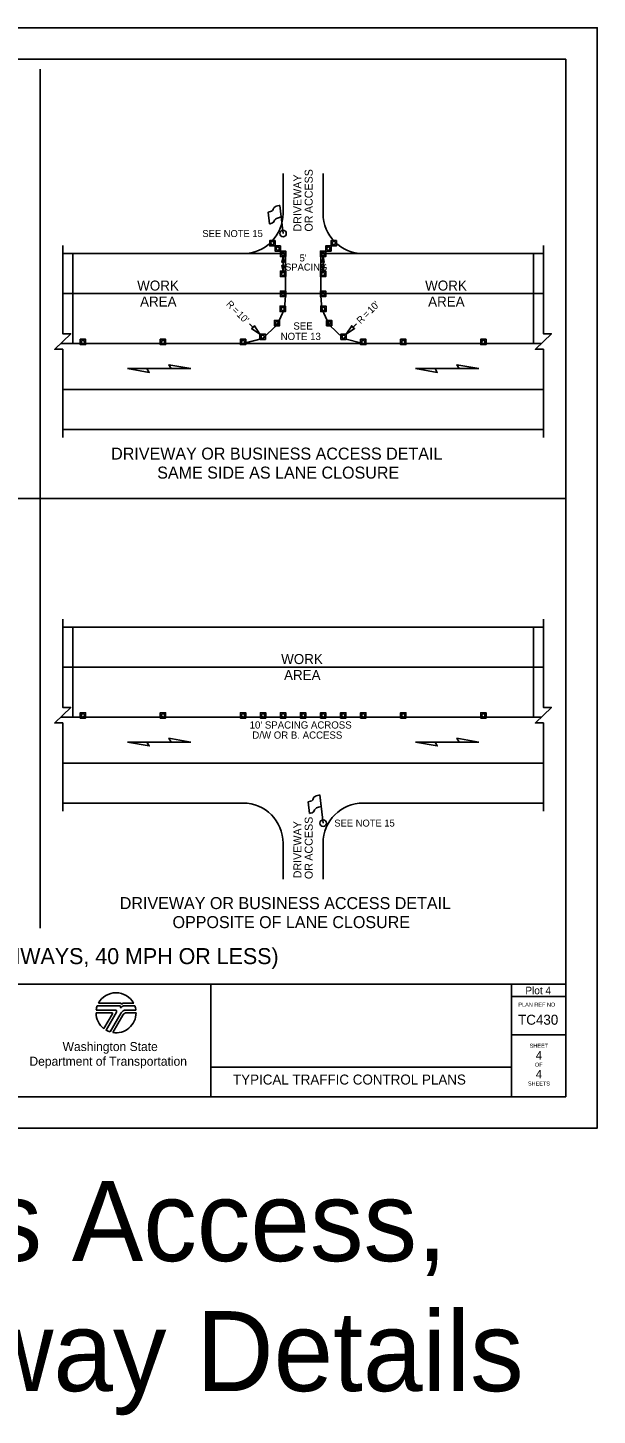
# Model space of a CAD drawing. Extents: x 99999.1 to 100095.7, y 99995 to 100010.7.
# Drawn here: x 100070.38 to 100076.06, y 99996.82 to 100010.69 of the extents above; entities that cross this region are included whole.
import ezdxf

# ---------------------------------------------------------------- set-up
doc = ezdxf.new("R2010")
doc.units = 0
for name, color, linetype in [('RD_ED_DrivewayEdge', 7, 'Continuous'), ('RD_ED_ShoulderPavedEdge', 7, 'Continuous'), ('RD_MK_LineEdgeWhite', 7, 'Continuous'), ('RD_MK_LineSkipCenter', 7, 'Continuous'), ('SH_DE_DetailHeading1Text', 7, 'Continuous'), ('SH_DE_DetailHeading2Text', 7, 'Continuous'), ('SH_GI_PlotLimits', 7, 'Continuous'), ('SH_GI_SheetBorder', 7, 'Continuous'), ('SH_GI_SheetLocationText', 7, 'Continuous'), ('SH_GI_SheetTextInCells', 7, 'Continuous'), ('SH_GI_TitleBlockText', 7, 'Continuous'), ('SH_GI_WSDOTLogo', 7, 'Continuous'), ('TR_WZ_FlaggingStation', 7, 'Continuous'), ('TR_WZ_TrafficCone', 7, 'Continuous'), ('TR_WZ_WorkAreaLabel', 7, 'Continuous'), ('TR_WZ_WorkZoneDetails', 7, 'Continuous'), ('TR_WZ_WorkZoneTextCurrent', 7, 'Continuous')]:
    doc.layers.add(name, color=color, linetype=linetype)

msp = doc.modelspace()

# ---------------------------------------------------------------- linework, layer by layer
at = {"layer": 'RD_ED_DrivewayEdge'}
for p, q in [((100072.925, 100008.83), (100072.925, 100009.23)), ((100073.325, 100008.83), (100073.325, 100009.23)), ((100072.925, 100002.536), (100072.925, 100002.176)), ((100073.325, 100002.536), (100073.325, 100002.176))]:
    msp.add_line(p, q, dxfattribs=at)
for centre, start, end in [((100072.525, 100008.83), 270, 0), ((100073.725, 100008.83), 180, 270), ((100072.525, 100002.536), 0, 90), ((100073.725, 100002.536), 90, 180)]:
    msp.add_arc(centre, 0.4, start, end, dxfattribs=at)
at = {"layer": 'RD_ED_ShoulderPavedEdge'}
for p, q in [((100070.725, 100008.43), (100072.525, 100008.43)), ((100073.725, 100008.43), (100075.525, 100008.43)), ((100070.725, 100006.67), (100075.525, 100006.67)), ((100070.725, 100004.696), (100075.525, 100004.696)), ((100070.725, 100002.936), (100072.525, 100002.936)), ((100073.725, 100002.936), (100075.525, 100002.936))]:
    msp.add_line(p, q, dxfattribs=at)
at = {"layer": 'RD_MK_LineEdgeWhite'}
for p, q in [((100070.725, 100008.03), (100075.525, 100008.03)), ((100070.725, 100007.07), (100075.525, 100007.07)), ((100070.725, 100004.296), (100075.525, 100004.296)), ((100070.725, 100003.336), (100075.525, 100003.336))]:
    msp.add_line(p, q, dxfattribs=at)
at = {"layer": 'RD_MK_LineSkipCenter'}
for points in [[(100075.504, 100007.53), (100070.704, 100007.53)], [(100075.504, 100003.796), (100070.704, 100003.796)]]:
    msp.add_lwpolyline(points, dxfattribs=at)
at = {"layer": 'SH_GI_PlotLimits'}
msp.add_lwpolyline([(100059.062, 99999.687), (100076.062, 99999.687), (100076.062, 100010.687), (100059.062, 100010.687)], close=True, dxfattribs=at)
at = {"layer": 'SH_GI_SheetBorder'}
for p, q in [((100060, 100010.375), (100075.75, 100010.375)), ((100075.75, 100010.375), (100075.75, 100000)), ((100060, 100001.126), (100075.75, 100001.126)), ((100072.205, 100001.126), (100072.205, 100000)), ((100075.208, 100001.126), (100075.208, 100000)), ((100075.208, 100001.001), (100075.75, 100001.001)), ((100075.208, 100000.618), (100075.75, 100000.618)), ((100072.205, 100000.295), (100075.208, 100000.295)), ((100060, 100000), (100075.75, 100000))]:
    msp.add_line(p, q, dxfattribs=at)
at = {"layer": 'SH_GI_WSDOTLogo'}
for p, q in [((100071.059, 100000.866), (100071.25, 100000.866)), ((100071.289, 100000.909), (100071.07, 100000.909)), ((100071.303, 100000.935), (100071.081, 100000.935)), ((100071.433, 100000.935), (100071.335, 100000.935)), ((100071.445, 100000.909), (100071.343, 100000.909)), ((100071.343, 100000.909), (100071.343, 100000.909)), ((100071.356, 100000.866), (100071.456, 100000.866)), ((100071.057, 100000.84), (100071.215, 100000.84)), ((100071.222, 100000.828), (100071.136, 100000.681)), ((100071.261, 100000.846), (100071.157, 100000.667)), ((100071.199, 100000.649), (100071.309, 100000.839)), ((100071.224, 100000.643), (100071.324, 100000.816)), ((100071.365, 100000.839), (100071.457, 100000.839))]:
    msp.add_line(p, q, dxfattribs=at)
for centre, radius, start, end in [((100071.257, 100000.84), 0.2, 28.4787, 151.532), ((100071.257, 100000.84), 0.2, 159.696, 172.5057), ((100071.25, 100000.853), 0.0131, 329.7683, 90), ((100071.289, 100000.895), 0.0148, 327.8418, 89.9985), ((100071.343, 100000.861), 0.0484, 89.9953, 147.8238), ((100071.303, 100000.926), 0.00903, 329.8742, 90.0033), ((100071.356, 100000.812), 0.0542, 90, 149.9974), ((100071.335, 100000.907), 0.0287, 90.0072, 148.1676), ((100071.257, 100000.84), 0.2, 7.4943, 20.2941), ((100071.257, 100000.84), 0.2, 179.9986, 232.8433), ((100071.215, 100000.832), 0.0082, 329.7436, 90), ((100071.257, 100000.84), 0.2, 260.5455, 359.8086), ((100071.365, 100000.792), 0.0476, 90, 150.0543), ((100071.257, 100000.84), 0.2, 239.7929, 253.0448)]:
    msp.add_arc(centre, radius, start, end, dxfattribs=at)
at = {"layer": 'TR_WZ_FlaggingStation'}
for p, q in [((100072.906, 100008.797), (100072.893, 100008.912)), ((100072.925, 100008.63), (100072.893, 100008.911)), ((100072.775, 100008.844), (100072.788, 100008.727)), ((100072.906, 100008.797), (100072.906, 100008.797)), ((100073.175, 100002.949), (100073.188, 100002.832)), ((100073.325, 100002.736), (100073.293, 100003.017)), ((100073.306, 100002.903), (100073.293, 100003.017)), ((100073.306, 100002.903), (100073.306, 100002.903))]:
    msp.add_line(p, q, dxfattribs=at)
for points in [[(100072.893, 100008.912), (100072.887, 100008.91), (100072.869, 100008.907), (100072.856, 100008.903), (100072.846, 100008.897), (100072.837, 100008.892), (100072.832, 100008.885), (100072.827, 100008.877), (100072.827, 100008.871), (100072.821, 100008.862), (100072.811, 100008.854), (100072.798, 100008.849), (100072.775, 100008.844)], [(100072.788, 100008.727), (100072.796, 100008.728), (100072.814, 100008.733), (100072.83, 100008.743), (100072.836, 100008.754), (100072.84, 100008.764), (100072.849, 100008.775), (100072.86, 100008.781), (100072.878, 100008.788), (100072.906, 100008.797)], [(100073.293, 100003.017), (100073.287, 100003.016), (100073.269, 100003.012), (100073.256, 100003.008), (100073.246, 100003.002), (100073.237, 100002.997), (100073.232, 100002.991), (100073.227, 100002.983), (100073.227, 100002.977), (100073.221, 100002.967), (100073.211, 100002.96), (100073.198, 100002.955), (100073.175, 100002.949)], [(100073.188, 100002.832), (100073.196, 100002.834), (100073.214, 100002.838), (100073.23, 100002.849), (100073.236, 100002.859), (100073.24, 100002.87), (100073.249, 100002.88), (100073.26, 100002.887), (100073.278, 100002.894), (100073.306, 100002.903)]]:
    msp.add_lwpolyline(points, dxfattribs=at)
for centre in [(100072.925, 100008.63), (100073.325, 100002.736)]:
    msp.add_circle(centre, 0.0325, dxfattribs=at)
at = {"layer": 'TR_WZ_TrafficCone'}
for points in [[(100072.845, 100008.56), (100072.845, 100008.507), (100072.792, 100008.507), (100072.792, 100008.56), (100072.845, 100008.56)], [(100072.792, 100008.56), (100072.792, 100008.507), (100072.845, 100008.507), (100072.845, 100008.56), (100072.792, 100008.56)], [(100072.898, 100008.507), (100072.898, 100008.454), (100072.845, 100008.454), (100072.845, 100008.507), (100072.898, 100008.507)], [(100072.845, 100008.507), (100072.845, 100008.454), (100072.898, 100008.454), (100072.898, 100008.507), (100072.845, 100008.507)], [(100073.352, 100008.507), (100073.352, 100008.454), (100073.405, 100008.454), (100073.405, 100008.507), (100073.352, 100008.507)], [(100073.405, 100008.507), (100073.405, 100008.454), (100073.352, 100008.454), (100073.352, 100008.507), (100073.405, 100008.507)], [(100073.405, 100008.56), (100073.405, 100008.507), (100073.458, 100008.507), (100073.458, 100008.56), (100073.405, 100008.56)], [(100073.458, 100008.56), (100073.458, 100008.507), (100073.405, 100008.507), (100073.405, 100008.56), (100073.458, 100008.56)], [(100072.898, 100008.454), (100072.952, 100008.454), (100072.952, 100008.4), (100072.898, 100008.4), (100072.898, 100008.454)], [(100072.898, 100008.4), (100072.952, 100008.4), (100072.952, 100008.454), (100072.898, 100008.454), (100072.898, 100008.4)], [(100073.352, 100008.454), (100073.298, 100008.454), (100073.298, 100008.4), (100073.352, 100008.4), (100073.352, 100008.454)], [(100073.352, 100008.4), (100073.298, 100008.4), (100073.298, 100008.454), (100073.352, 100008.454), (100073.352, 100008.4)], [(100072.898, 100008.254), (100072.952, 100008.254), (100072.952, 100008.2), (100072.898, 100008.2), (100072.898, 100008.254)], [(100072.898, 100008.2), (100072.952, 100008.2), (100072.952, 100008.254), (100072.898, 100008.254), (100072.898, 100008.2)], [(100073.352, 100008.254), (100073.298, 100008.254), (100073.298, 100008.2), (100073.352, 100008.2), (100073.352, 100008.254)], [(100073.352, 100008.2), (100073.298, 100008.2), (100073.298, 100008.254), (100073.352, 100008.254), (100073.352, 100008.2)], [(100072.898, 100008.054), (100072.952, 100008.054), (100072.952, 100008), (100072.898, 100008), (100072.898, 100008.054)], [(100072.898, 100008), (100072.952, 100008), (100072.952, 100008.054), (100072.898, 100008.054), (100072.898, 100008)], [(100073.352, 100008.054), (100073.298, 100008.054), (100073.298, 100008), (100073.352, 100008), (100073.352, 100008.054)], [(100073.352, 100008), (100073.298, 100008), (100073.298, 100008.054), (100073.352, 100008.054), (100073.352, 100008)], [(100072.896, 100007.904), (100072.949, 100007.904), (100072.949, 100007.85), (100072.896, 100007.85), (100072.896, 100007.904)], [(100072.896, 100007.85), (100072.949, 100007.85), (100072.949, 100007.904), (100072.896, 100007.904), (100072.896, 100007.85)], [(100073.354, 100007.904), (100073.301, 100007.904), (100073.301, 100007.85), (100073.354, 100007.85), (100073.354, 100007.904)], [(100073.354, 100007.85), (100073.301, 100007.85), (100073.301, 100007.904), (100073.354, 100007.904), (100073.354, 100007.85)], [(100072.838, 100007.762), (100072.891, 100007.762), (100072.891, 100007.708), (100072.838, 100007.708), (100072.838, 100007.762)], [(100072.838, 100007.708), (100072.891, 100007.708), (100072.891, 100007.762), (100072.838, 100007.762), (100072.838, 100007.708)], [(100073.412, 100007.762), (100073.359, 100007.762), (100073.359, 100007.708), (100073.412, 100007.708), (100073.412, 100007.762)], [(100073.412, 100007.708), (100073.359, 100007.708), (100073.359, 100007.762), (100073.412, 100007.762), (100073.412, 100007.708)], [(100070.899, 100007.574), (100070.952, 100007.574), (100070.952, 100007.52), (100070.899, 100007.52), (100070.899, 100007.574)], [(100070.899, 100007.52), (100070.952, 100007.52), (100070.952, 100007.574), (100070.899, 100007.574), (100070.899, 100007.52)], [(100071.699, 100007.574), (100071.752, 100007.574), (100071.752, 100007.52), (100071.699, 100007.52), (100071.699, 100007.574)], [(100071.699, 100007.52), (100071.752, 100007.52), (100071.752, 100007.574), (100071.699, 100007.574), (100071.699, 100007.52)], [(100072.499, 100007.574), (100072.552, 100007.574), (100072.552, 100007.52), (100072.499, 100007.52), (100072.499, 100007.574)], [(100072.499, 100007.52), (100072.552, 100007.52), (100072.552, 100007.574), (100072.499, 100007.574), (100072.499, 100007.52)], [(100072.694, 100007.625), (100072.748, 100007.625), (100072.748, 100007.571), (100072.694, 100007.571), (100072.694, 100007.625)], [(100072.694, 100007.571), (100072.748, 100007.571), (100072.748, 100007.625), (100072.694, 100007.625), (100072.694, 100007.571)], [(100073.556, 100007.625), (100073.502, 100007.625), (100073.502, 100007.571), (100073.556, 100007.571), (100073.556, 100007.625)], [(100073.556, 100007.571), (100073.502, 100007.571), (100073.502, 100007.625), (100073.556, 100007.625), (100073.556, 100007.571)], [(100073.699, 100007.574), (100073.752, 100007.574), (100073.752, 100007.52), (100073.699, 100007.52), (100073.699, 100007.574)], [(100073.699, 100007.52), (100073.752, 100007.52), (100073.752, 100007.574), (100073.699, 100007.574), (100073.699, 100007.52)], [(100074.099, 100007.574), (100074.152, 100007.574), (100074.152, 100007.52), (100074.099, 100007.52), (100074.099, 100007.574)], [(100074.099, 100007.52), (100074.152, 100007.52), (100074.152, 100007.574), (100074.099, 100007.574), (100074.099, 100007.52)], [(100074.899, 100007.574), (100074.952, 100007.574), (100074.952, 100007.52), (100074.899, 100007.52), (100074.899, 100007.574)], [(100074.899, 100007.52), (100074.952, 100007.52), (100074.952, 100007.574), (100074.899, 100007.574), (100074.899, 100007.52)], [(100070.899, 100003.839), (100070.952, 100003.839), (100070.952, 100003.786), (100070.899, 100003.786), (100070.899, 100003.839)], [(100070.899, 100003.786), (100070.952, 100003.786), (100070.952, 100003.839), (100070.899, 100003.839), (100070.899, 100003.786)], [(100071.699, 100003.839), (100071.752, 100003.839), (100071.752, 100003.786), (100071.699, 100003.786), (100071.699, 100003.839)], [(100071.699, 100003.786), (100071.752, 100003.786), (100071.752, 100003.839), (100071.699, 100003.839), (100071.699, 100003.786)], [(100072.499, 100003.839), (100072.552, 100003.839), (100072.552, 100003.786), (100072.499, 100003.786), (100072.499, 100003.839)], [(100072.499, 100003.786), (100072.552, 100003.786), (100072.552, 100003.839), (100072.499, 100003.839), (100072.499, 100003.786)], [(100072.699, 100003.839), (100072.752, 100003.839), (100072.752, 100003.786), (100072.699, 100003.786), (100072.699, 100003.839)], [(100072.699, 100003.786), (100072.752, 100003.786), (100072.752, 100003.839), (100072.699, 100003.839), (100072.699, 100003.786)], [(100072.899, 100003.839), (100072.952, 100003.839), (100072.952, 100003.786), (100072.899, 100003.786), (100072.899, 100003.839)], [(100072.899, 100003.786), (100072.952, 100003.786), (100072.952, 100003.839), (100072.899, 100003.839), (100072.899, 100003.786)], [(100073.099, 100003.839), (100073.152, 100003.839), (100073.152, 100003.786), (100073.099, 100003.786), (100073.099, 100003.839)], [(100073.099, 100003.786), (100073.152, 100003.786), (100073.152, 100003.839), (100073.099, 100003.839), (100073.099, 100003.786)], [(100073.299, 100003.839), (100073.352, 100003.839), (100073.352, 100003.786), (100073.299, 100003.786), (100073.299, 100003.839)], [(100073.299, 100003.786), (100073.352, 100003.786), (100073.352, 100003.839), (100073.299, 100003.839), (100073.299, 100003.786)], [(100073.499, 100003.839), (100073.552, 100003.839), (100073.552, 100003.786), (100073.499, 100003.786), (100073.499, 100003.839)], [(100073.499, 100003.786), (100073.552, 100003.786), (100073.552, 100003.839), (100073.499, 100003.839), (100073.499, 100003.786)], [(100073.699, 100003.839), (100073.752, 100003.839), (100073.752, 100003.786), (100073.699, 100003.786), (100073.699, 100003.839)], [(100073.699, 100003.786), (100073.752, 100003.786), (100073.752, 100003.839), (100073.699, 100003.839), (100073.699, 100003.786)], [(100074.099, 100003.839), (100074.152, 100003.839), (100074.152, 100003.786), (100074.099, 100003.786), (100074.099, 100003.839)], [(100074.099, 100003.786), (100074.152, 100003.786), (100074.152, 100003.839), (100074.099, 100003.839), (100074.099, 100003.786)], [(100074.899, 100003.839), (100074.952, 100003.839), (100074.952, 100003.786), (100074.899, 100003.786), (100074.899, 100003.839)], [(100074.899, 100003.786), (100074.952, 100003.786), (100074.952, 100003.839), (100074.899, 100003.839), (100074.899, 100003.786)]]:
    msp.add_lwpolyline(points, dxfattribs=at)
for centre in [(100072.818, 100008.534), (100072.872, 100008.48), (100073.378, 100008.48), (100073.432, 100008.534), (100072.925, 100008.427), (100073.325, 100008.427), (100072.925, 100008.227), (100073.325, 100008.227), (100072.925, 100008.027), (100073.325, 100008.027), (100072.922, 100007.877), (100073.328, 100007.877), (100072.865, 100007.735), (100073.385, 100007.735), (100070.926, 100007.547), (100071.726, 100007.547), (100072.526, 100007.547), (100072.721, 100007.598), (100073.529, 100007.598), (100073.726, 100007.547), (100074.126, 100007.547), (100074.926, 100007.547), (100070.926, 100003.813), (100071.726, 100003.813), (100072.526, 100003.813), (100072.726, 100003.813), (100072.926, 100003.813), (100073.126, 100003.813), (100073.326, 100003.813), (100073.526, 100003.813), (100073.726, 100003.813), (100074.126, 100003.813), (100074.926, 100003.813)]:
    msp.add_circle(centre, 0.0167, dxfattribs=at)
at = {"layer": 'TR_WZ_WorkZoneDetails'}
for p, q in [((100070.5, 100010.275), (100070.5, 100001.686)), ((100072.925, 100008.346), (100072.925, 100008.308)), ((100073.325, 100008.346), (100073.325, 100008.308)), ((100072.628, 100007.691), (100072.59, 100007.729)), ((100073.622, 100007.691), (100073.66, 100007.729)), ((100071.566, 100007.28), (100071.808, 100007.28)), ((100071.808, 100007.28), (100071.566, 100007.28)), ((100074.443, 100007.28), (100074.684, 100007.28)), ((100074.684, 100007.28), (100074.443, 100007.28)), ((100070.5, 100005.98), (100065.25, 100005.98)), ((100075.75, 100005.98), (100070.5, 100005.98)), ((100071.566, 100003.546), (100071.808, 100003.546)), ((100071.808, 100003.546), (100071.566, 100003.546)), ((100074.443, 100003.546), (100074.684, 100003.546)), ((100074.684, 100003.546), (100074.443, 100003.546))]:
    msp.add_line(p, q, dxfattribs=at)
for points in [[(100070.725, 100006.59), (100070.725, 100007.473), (100070.645, 100007.473), (100070.805, 100007.628), (100070.725, 100007.628), (100070.725, 100008.51)], [(100075.525, 100006.59), (100075.525, 100007.473), (100075.445, 100007.473), (100075.605, 100007.628), (100075.525, 100007.628), (100075.525, 100008.51)], [(100070.725, 100002.856), (100070.725, 100003.738), (100070.645, 100003.738), (100070.805, 100003.893), (100070.725, 100003.893), (100070.725, 100004.776)], [(100075.525, 100002.856), (100075.525, 100003.738), (100075.445, 100003.738), (100075.605, 100003.893), (100075.525, 100003.893), (100075.525, 100004.776)]]:
    msp.add_lwpolyline(points, dxfattribs=at)
for points in [[(100072.948, 100008.43), (100072.948, 100008.207), (100072.948, 100008.007), (100072.939, 100007.877), (100072.939, 100007.877), (100072.939, 100007.877), (100072.865, 100007.718), (100072.865, 100007.718), (100072.865, 100007.718), (100072.721, 100007.581), (100072.526, 100007.53), (100071.529, 100007.53), (100070.949, 100007.53), (100070.825, 100007.53), (100070.825, 100008.43)], [(100072.925, 100008.4), (100072.936, 100008.343), (100072.925, 100008.346), (100072.914, 100008.343)], [(100075.425, 100008.43), (100075.425, 100008.03), (100075.425, 100007.53), (100074.501, 100007.53), (100074.501, 100007.53), (100074.501, 100007.53), (100073.726, 100007.53), (100073.726, 100007.53), (100073.726, 100007.53), (100073.529, 100007.581), (100073.385, 100007.718), (100073.311, 100007.877), (100073.302, 100008.007), (100073.302, 100008.207), (100073.302, 100008.43)], [(100073.325, 100008.4), (100073.336, 100008.343), (100073.325, 100008.346), (100073.314, 100008.343)], [(100072.925, 100008.254), (100072.936, 100008.311), (100072.925, 100008.308), (100072.914, 100008.311)], [(100073.325, 100008.254), (100073.336, 100008.311), (100073.325, 100008.308), (100073.314, 100008.311)], [(100072.694, 100007.625), (100072.611, 100007.681), (100072.628, 100007.691), (100072.639, 100007.708)], [(100073.556, 100007.625), (100073.639, 100007.681), (100073.622, 100007.691), (100073.611, 100007.708)], [(100071.37, 100007.28), (100071.589, 100007.242), (100071.566, 100007.28)], [(100072.004, 100007.28), (100071.785, 100007.319), (100071.808, 100007.28)], [(100074.247, 100007.28), (100074.465, 100007.242), (100074.443, 100007.28)], [(100074.881, 100007.28), (100074.662, 100007.319), (100074.684, 100007.28)], [(100070.825, 100004.696), (100070.825, 100003.796), (100075.425, 100003.796), (100075.425, 100004.696)], [(100071.37, 100003.546), (100071.589, 100003.507), (100071.566, 100003.546)], [(100072.004, 100003.546), (100071.785, 100003.584), (100071.808, 100003.546)], [(100074.247, 100003.546), (100074.465, 100003.507), (100074.443, 100003.546)], [(100074.881, 100003.546), (100074.662, 100003.584), (100074.684, 100003.546)]]:
    msp.add_lwpolyline(points, close=True, dxfattribs=at)

# ---------------------------------------------------------------- texts
at = {"layer": 'SH_DE_DetailHeading1Text'}
msp.add_text('ALTERNATING 1-LANE, 2-WAY TRAFFIC: AFAD-CONTROLLED (HIGH VOLUME HIGHWAYS, 40 MPH OR LESS)', height=0.16, rotation=360, dxfattribs=at).set_placement((100061.789, 100001.326))
at = {"layer": 'SH_DE_DetailHeading2Text'}
for s, p in [('DRIVEWAY OR BUSINESS ACCESS DETAIL', (100071.208, 100006.37)), ('SAME SIDE AS LANE CLOSURE', (100071.668, 100006.18)), ('DRIVEWAY OR BUSINESS ACCESS DETAIL', (100071.294, 100001.876)), ('OPPOSITE OF LANE CLOSURE', (100071.821, 100001.686))]:
    msp.add_text(s, height=0.12, rotation=360, dxfattribs=at).set_placement(p)
at = {"layer": 'SH_GI_SheetBorder'}
msp.add_text('PLAN REF NO', height=0.04003, dxfattribs=at).set_placement((100075.275, 100000.901))
at = {"layer": 'SH_GI_SheetLocationText'}
for s, height, p in [('Plot 4', 0.075, (100075.345, 100001.025)), ('Driveway, Business Access,', 0.8, (100061.184, 99998.357)), ('or Intersecting Roadway Details', 0.8, (100060.225, 99997.057))]:
    msp.add_text(s, height=height, dxfattribs=at).set_placement(p)
at = {"layer": 'SH_GI_SheetTextInCells'}
for s, height, p in [('Washington State', 0.09007, (100070.723, 100000.457)), ('SHEET', 0.04, (100075.388, 100000.49)), ('Department of Transportation', 0.09007, (100070.392, 100000.31)), ('OF', 0.04, (100075.441, 100000.301)), ('SHEETS', 0.04, (100075.37, 100000.112))]:
    msp.add_text(s, height=height, dxfattribs=at).set_placement(p)
at = {"layer": 'SH_GI_TitleBlockText'}
for s, height, p in [('TC430', 0.1, (100075.272, 100000.72)), ('4', 0.085, (100075.449, 100000.372)), ('TYPICAL TRAFFIC CONTROL PLANS', 0.1, (100072.425, 100000.122)), ('4', 0.085, (100075.449, 100000.184))]:
    msp.add_text(s, height=height, dxfattribs=at).set_placement(p)
at = {"layer": 'TR_WZ_WorkAreaLabel'}
for s, p in [('WORK', (100071.468, 100008.06)), ('WORK', (100074.344, 100008.06)), ('AREA', (100071.497, 100007.9)), ('AREA', (100074.374, 100007.9)), ('WORK', (100072.906, 100004.326)), ('AREA', (100072.935, 100004.166))]:
    msp.add_text(s, height=0.1, dxfattribs=at).set_placement(p)
at = {"layer": 'TR_WZ_WorkZoneTextCurrent'}
for s, height, rotation, p in [('DRIVEWAY', 0.08, 90, (100073.109, 100008.65)), ('ACCESS', 0.08, 90, (100073.221, 100008.834)), ('OR', 0.08, 90, (100073.221, 100008.65)), ('R', 0.07, 315, (100072.351, 100007.919)), ("10'", 0.07, 45, (100073.808, 100007.827)), ('=', 0.07, 315, (100072.41, 100007.859)), ("10'", 0.07, 315, (100072.457, 100007.813)), ('R', 0.07, 45, (100073.701, 100007.721)), ('=', 0.07, 45, (100073.761, 100007.78)), ('ACCESS', 0.08, 90, (100073.221, 100002.36)), ('DRIVEWAY', 0.08, 90, (100073.109, 100002.184)), ('OR', 0.08, 90, (100073.221, 100002.176))]:
    msp.add_text(s, height=height, rotation=rotation, dxfattribs=at).set_placement(p)
for s, height, p in [('SEE NOTE 15', 0.07, (100072.119, 100008.595)), ("5'", 0.07, (100073.09, 100008.351)), ('SPACING', 0.07, (100072.945, 100008.26)), ('SEE', 0.072, (100073.028, 100007.67)), ('NOTE 13', 0.072, (100072.901, 100007.566)), ("10' SPACING ACROSS", 0.072, (100072.591, 100003.681)), ('D/W OR B. ACCESS', 0.072, (100072.618, 100003.58)), ('SEE NOTE 15', 0.07, (100073.437, 100002.701))]:
    msp.add_text(s, height=height, dxfattribs=at).set_placement(p)

doc.saveas('drawing.dxf')
